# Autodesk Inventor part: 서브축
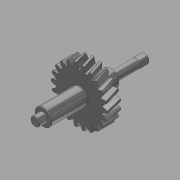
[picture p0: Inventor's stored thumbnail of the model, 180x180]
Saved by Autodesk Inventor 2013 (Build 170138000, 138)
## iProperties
Created: 2017-11
Part Number: 서브축
Material: 강철, 탄소
Document SubType Name: Modeling
Designer: mduedu
Categories: <?xml version="1.0" encoding="UTF-16"?> <MemberInstance><Categories><FamilyTemplate><FamilyTemplateParameter ValueType="xs:double" Id="1" ObjectReferenceKey="da
Density: 1 g/cm^3
CustomPartVersion: 1
Author: mduedu
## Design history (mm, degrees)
sketch "Sketch1"
  geometry: C1 r 24.776 at (0, 0)
  constraints: 1 centre point
  dimensions: "d0" = 49.55215 diameter of C1 (= da_da)
extrude "Extrusion1" new body sketch "Sketch1" distance "d1" = 12 (= da_b); taper "d2" = 0 deg
workplane "Work Plane2"
sketch "Sketch2"
  geometry: C1 r 24.776 at (0, 0) reference; C2 r 22.776 at (0, 0)
  constraints: 1 centre point, 1 coincident
  dimensions: "d3" = 45.55215 diameter of C2 (= da_dw)
feature "피치 지름" sketch "Sketch2" dims "d4" = 10, "d5" = 0
workplane "Work Plane8"
workplane "Work Plane9"
feature "스퍼 기어" dims "da_b" = 12, "da_d" = 45.55215, "da_aw" = 54.86964, "da_da" = 49.55215, "da_df" = 40.55215, "da_dw" = 45.55215, angle "da_beta" = 15 deg, "da_lefttooth" = 10, "da_righttooth" = 0
sketch "스케치3"
  geometry: C1 r 7.5 at (0, 0); 1 further point
  constraints: 1 centre point, 1 coincident
  dimensions: "d49" = 15 diameter of C1
extrude "돌출2" join sketch "스케치3" distance "d50" = 32; taper "d51" = 0 deg
sketch "스케치4"
  geometry: C1 r 4 at (0, 0); 1 further point
  constraints: 1 centre point, 1 coincident
  dimensions: "d52" = 8 diameter of C1
extrude "돌출3" join sketch "스케치4" distance "d53" = 7; taper "d54" = 0 deg
sketch "스케치5"
  geometry: C1 r 7.5 at (0, 0); 1 further point
  constraints: 1 centre point, 1 coincident
  dimensions: "d55" = 15 diameter of C1
extrude "돌출4" join sketch "스케치5" distance "d56" = 16; taper "d57" = 0 deg
sketch "스케치6"
  geometry: C1 r 4 at (0, 0); 1 further point
  constraints: 1 centre point, 1 coincident
  dimensions: "d58" = 8 diameter of C1
extrude "돌출5" join sketch "스케치6" distance "d59" = 30; taper "d60" = 0 deg
chamfer "모따기1" distance "d61" = 0.5; stored, may be unused: second distance "d62" = 2, angle "d63" = 45 deg
fillet "모깎기1" dims "d64" = 0.5
sketch "스케치7"
  geometry: L1 (-3.25, -3.25)-(3.25, -3.25); L2 (3.25, -3.25)-(3.25, 3.25); L3 (3.25, 3.25)-(-3.25, 3.25); L4 (-3.25, 3.25)-(-3.25, -3.25); L5 (-3.25, -3.25)-(3.25, 3.25); L6 (3.25, -3.25)-(-3.25, 3.25); L7 (-5, -5)-(5, -5); L8 (5, -5)-(5, 5); L9 (5, 5)-(-5, 5); L10 (-5, 5)-(-5, -5); L11 (-5, -5)-(5, 5); L12 (5, -5)-(-5, 5); 1 further point
  constraints: 24 end point, 4 midpoint, 4 parallel, 2 horizontal, 2 perpendicular
  dimensions: "d65" = 6.5 distance of L3.end L2.end; "d66" = 6.5 distance of L2.end L1.end; "d67" = 10 distance of L9.end L8.end; "d68" = 10 distance of L8.end L7.end
extrude "돌출6" cut sketch "스케치7" distance "d69" = 8; taper "d70" = 0 deg
body "Solid1"
body "Srf1"
other parameters: "d16" = 54.86964 (= da_aw), "d17" = 0, "d34" = 1.428 (computed from da_z), "d39" = 0, "d41" = 0, "d43" = 54.86964 (= da_aw), "d46" = 54.86964 (= da_aw), "d47" = 0, "d48" = 0
